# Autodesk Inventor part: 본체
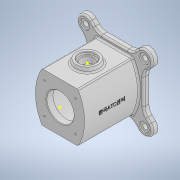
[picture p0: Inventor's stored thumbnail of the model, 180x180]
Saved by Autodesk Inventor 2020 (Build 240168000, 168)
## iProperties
Created: 2022-01
Part Number: 본체
Material: 일반
Document SubType Name: Modeling
Designer: user
Density: 1 g/cm^3
Appearance: 기본값
Mass: 458.999 g
Surface Area: 907.713 cm^2
Volume: 458.999 cm^3
Author: user
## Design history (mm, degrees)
sketch "스케치1"
  geometry: L1 (-45, -45)-(45, -45); L2 (45, -45)-(45, 45); L3 (45, 45)-(-32.942, 45); L4 (-45, 45)-(-45, -45); L5 (-45, -45)-(45, 45); L6 (45, -45)-(-45, 45); A1 r 90 centre (45, 0) between (-32.942, 45) and (-32.942, -45); A2 r 90 centre (-45, 0) between (32.942, -45) and (32.942, 45); 12 further points
  constraints: 12 end point, 10 point on circle, 7 point on line, 6 midpoint, 3 coincident, 3 vertical alignment, 2 centre point, 2 parallel, 1 horizontal, 1 horizontal alignment, 1 perpendicular
  dimensions: "d0" = 90 distance of L4.start L2.end; "d1" = 90 distance of L2.end L1.end
extrude "돌출1" new body sketch "스케치1" stored distance "d5" = 100; taper "d6" = 0 deg
sketch "스케치2"
  geometry: L1 (-53, -53)-(53, -53); L2 (53, -53)-(53, 53); L3 (53, 53)-(-53, 53); L4 (-53, 53)-(-53, -53); L5 (-53, -53)-(53, 53); L6 (53, -53)-(-53, 53); L7 (54.447, -54.447)-(-54.447, 54.447); L8 (65.054, -43.841)-(-43.841, 65.054); L9 (-65.054, 43.841)-(43.841, -65.054); L10 (-54.447, -54.447)-(54.447, 54.447); L11 (-43.841, -65.054)-(65.054, 43.841); L12 (43.841, 65.054)-(-65.054, -43.841); A1 r 15 centre (54.447, -54.447) between (43.841, -65.054) and (65.054, -43.841); A2 r 15 centre (-54.447, 54.447) between (-43.841, 65.054) and (-65.054, 43.841); A3 r 15 centre (-54.447, -54.447) between (-65.054, -43.841) and (-43.841, -65.054); A4 r 15 centre (54.447, 54.447) between (65.054, 43.841) and (43.841, 65.054); A5 r 77 centre (0, 0) between (-42.798, 64.011) and (-64.011, 42.798); A6 r 77 centre (0, 0) between (64.011, 42.798) and (42.798, 64.011); A7 r 77 centre (0, 0) between (-64.011, -42.798) and (-42.798, -64.011); A8 r 77 centre (0, 0) between (42.798, -64.011) and (64.011, -42.798); 9 further points
  constraints: 28 end point, 18 point on circle, 10 point on line, 8 centre point, 8 tangent, 4 midpoint, 4 parallel, 1 coincident, 1 horizontal, 1 perpendicular
  dimensions: "d7" = 106 distance of L3.end L2.end; "d8" = 106 distance of L2.end L1.end; "d10" = 30 diameter of A2; "d11" = 30 diameter of A4
extrude "돌출2" join sketch "스케치2" distance "d12" = 10; taper "d13" = 0 deg
sketch "스케치3"
  geometry: 1 further point
sketch "스케치4"
  geometry: 1 further point
node "작업 평면1"
sketch "스케치5"
  geometry: C1 r 20 at (0, 0); 1 further point
  constraints: 1 centre point, 1 coincident
  dimensions: "d15" = 40 diameter of C1
extrude "돌출3" join sketch "스케치5" stored distance "d16" = 10; taper "d17" = 15 deg
sketch "스케치6"
  geometry: C1 r 25 at (0, 0); 1 further point
  constraints: 1 centre point, 1 coincident
  dimensions: "d18" = 50 diameter of C1
extrude "돌출4" cut sketch "스케치6" distance "d19" = 12; taper "d20" = 0 deg
sketch "스케치7"
  geometry: C1 r 37 at (0, 0); 1 further point
  constraints: 1 centre point, 1 coincident
  dimensions: "d21" = 74 diameter of C1
extrude "돌출5" cut sketch "스케치7" distance "d22" = 86; taper "d23" = 0 deg
sketch "스케치8"
  geometry: C1 r 25 at (0, 0); 1 further point
  constraints: 1 centre point, 1 coincident
  dimensions: "d24" = 50 diameter of C1
extrude "돌출6" cut sketch "스케치8" distance "d25" = 12; taper "d26" = 0 deg
sketch "스케치9"
  geometry: L1 (0, 0)-(-28.284, 28.284); L2 (0, 0)-(40, 0); L3 (0, 0)-(28.284, 28.284); L4 (0, 0)-(40, 0)
  constraints: 8 end point, 2 equal length, 2 horizontal
  dimensions: "d27" = 40 distance of L1.start L1.end; "d28" = 135 deg angle of L2 L1; "d29" = 40 distance of L1.start L3.end; "d30" = 45 deg angle of L4 L3
hole "구멍1" sketch "스케치9" at (-28.284, 28.284), (28.284, 28.284) diameter "d31" = 3.242; stored, may be unused: countersink angle "d35" = 90 deg, drill point angle "d37" = 118 deg; dims "d32" = 8, "d33" = 4, "d34" = 2, "d36" = 10
sketch "스케치10"
  geometry: L1 (0, 0)-(-28.284, 28.284); L2 (0, 0)-(40, 0); L3 (0, 0)-(28.284, 28.284); L4 (0, 0)-(40, 0)
  constraints: 8 end point, 2 equal length, 2 horizontal
  dimensions: "d38" = 40 distance of L1.start L1.end; "d39" = 135 deg angle of L2 L1; "d40" = 40 distance of L1.start L3.end; "d41" = 45 deg angle of L4 L3
hole "구멍2" sketch "스케치10" at (28.284, 28.284), (-28.284, 28.284) diameter "d42" = 3.242; stored, may be unused: countersink angle "d46" = 90 deg, drill point angle "d48" = 118 deg; dims "d43" = 8, "d44" = 4, "d45" = 2, "d47" = 10
sketch "스케치11"
  geometry: A1 r 15 centre (54.447, 54.447) between (65.054, 43.841) and (43.841, 65.054) reference; A2 r 15 centre (-54.447, 54.447) between (-43.841, 65.054) and (-65.054, 43.841) reference; A3 r 15 centre (54.447, -54.447) between (43.841, -65.054) and (65.054, -43.841) reference; A4 r 15 centre (-54.447, -54.447) between (-65.054, -43.841) and (-43.841, -65.054) reference; 5 further points
  constraints: 4 coincident
hole "구멍3" sketch "스케치11" at (54.447, 54.447), (-54.447, 54.447), (54.447, -54.447), (-54.447, -54.447) diameter "d49" = 9; stored, may be unused: countersink angle "d53" = 90 deg, drill point angle "d55" = 0 deg; dims "d50" = 8, "d51" = 18, "d52" = 2, "d54" = 10
sketch "스케치12"
  geometry: C1 r 15 at (0, 0); 1 further point
  constraints: 1 centre point, 1 coincident
  dimensions: "d56" = 30 diameter of C1
extrude "돌출7" cut sketch "스케치12" distance "d57" = 5; taper "d58" = 0 deg
sketch "스케치13"
  geometry: C1 r 15 at (0, 0) reference; C2 r 12 at (0, 0); 1 further point
  constraints: 1 centre point, 1 coincident
  dimensions: "d59" = 24 diameter of C2
extrude "돌출8" cut sketch "스케치13" stored distance "d60" = 5; taper "d61" = 0 deg
chamfer "모따기1" distance "d62" = 1; stored, may be unused: second distance "d63" = 2, angle "d64" = 45 deg
chamfer "모따기2" distance "d65" = 1; stored, may be unused: second distance "d66" = 2, angle "d67" = 45 deg
fillet "모깎기1" dims "d68" = 3
fillet "모깎기2" dims "d69" = 3
fillet "모깎기3" dims "d70" = 3
fillet "모깎기4" dims "d71" = 20
fillet "모깎기5" dims "d72" = 3
node "작업 평면3"
sketch "스케치14"
  geometry: L1 (53, -20)-(53, 20) reference; L2 (23.503, -60)-(37.645, -60) reference; 2 further points
  constraints: 1 other
  dimensions: "d75" = 53 distance from line of L1 point (0, 0); "d76" = 60 distance from line of point (0, 0) L2
feature "엠보싱1" sketch "스케치14" dims "d0" = 90, "d1" = 90, "d7" = 106, "d8" = 106, "d10" = 30, "d11" = 30, "d77" = 0.5, "d78" = 0
fillet "모깎기6" dims "d79" = 3
node "솔리드1"
mirror "미러1"
mirror "미러2"
feature "A9D066F2-1C7D-4E18-AEED-F7BC21143FA4" dims "d49" = 9, "d50" = 8, "d51" = 18, "d52" = 2, "d53" = 90 deg, "d54" = 10, "d55" = 0
other parameters: "d9" = 154, "d14" = 53, "d74" = 45
